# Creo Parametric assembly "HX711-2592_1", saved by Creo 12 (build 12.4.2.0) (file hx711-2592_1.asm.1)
Units: Custom; MM, KILOGRAM, SECS

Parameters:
  PTC_WM_ITERATION = "0"
  PTC_WM_VERSION = "-.0"
  PTC_WM_LIFECYCLE_STATE = "In Work"
  PTC_WM_LIFECYCLE = "MO_CADDocument"
  PTC_WM_CREATED_BY = "Maximilian Roepper (Z0017RMS: MO)"
  PTC_WM_CREATED_ON = "18-Sep-26 11:36:42 AM"
  PTC_WM_MODIFIED_BY = "Maximilian Roepper (Z0017RMS: MO)"
  PTC_WM_MODIFIED_ON = "18-Sep-26 11:36:46 AM"
  PDMLINKNUMBER = "PDM000071455076"
  PTC_WM_NUMBER = "PDM000071455076"

Other parameters: WEIGHT, WEIGHT_FACTOR, WEIGHT_ADD, MC_ERRORS, SUPPLIER

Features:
  1. coordinate system
  2. imported feature
  3. component "HX711-2615_1"

Other named items: DRW_VIEW_ORG, ROUGH-GROB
